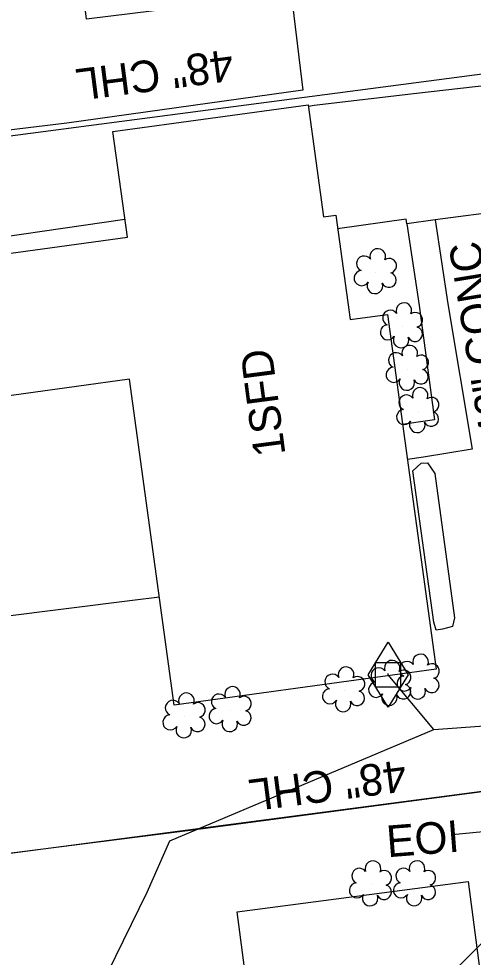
# Model space of a CAD drawing. Extents: x 2364404 to 2371833, y 798876 to 809754.
# Drawn here: x 2368310.1 to 2368367.6, y 807455.3 to 807574.1 of the extents above; entities that cross this region are included whole.
import ezdxf

# ---------------------------------------------------------------- set-up
doc = ezdxf.new("R2010")
doc.units = 0
for name, color, linetype in [('CTL Supplemental Horizontal and Vertical CELL', 7, 'Continuous'), ('Exist Building', 7, 'Continuous'), ('Exist Building Text', 7, 'Continuous'), ('Exist Other Culture Area Outline', 7, 'Continuous'), ('Exist Other Culture Area Outline Text', 7, 'Continuous'), ('Exist Other Culture Fence Line', 7, 'Continuous'), ('Exist Other Culture Fence Line Text', 7, 'Continuous'), ('Exist Property Line', 7, 'Continuous'), ('Exist Roads EOP Other', 7, 'Continuous'), ('Exist Utilities Gas Meter CELL', 7, 'Continuous'), ('Exist Utilities Gas UG Line SUE LOS B', 7, 'Continuous'), ('Exist Utilities Telephone UG Cable SUE LOS C', 7, 'Continuous'), ('Exist Utilities Telephone UG Cable SUE LOS C Text', 7, 'Continuous'), ('Exist Vegetation Hedge Row', 7, 'Continuous'), ('Exist Vegetation Shrub CELL', 7, 'Continuous')]:
    doc.layers.add(name, color=color, linetype=linetype)

msp = doc.modelspace()

# ---------------------------------------------------------------- linework, layer by layer
at = {"layer": 'CTL Supplemental Horizontal and Vertical CELL'}
msp.add_lwpolyline([(2368312.4, 807400.83), (2368379.23, 807467.66), (2368446.17, 807400.72), (2368379.35, 807333.89)], close=True, dxfattribs=at)
at = {"layer": 'Exist Building'}
for points in [[(2368318.69, 807574.03), (2368314.02, 807611.56), (2368304.65, 807610.39), (2368302.81, 807625.16), (2368311.97, 807626.3), (2368311.81, 807627.59), (2368339.99, 807631.09), (2368341.48, 807619.07), (2368346.02, 807619.64), (2368349.22, 807593.91), (2368344.46, 807593.32), (2368346.43, 807577.48)], [(2368329.78, 807487.21), (2368324.12, 807528.47), (2368303.93, 807525.7), (2368303.52, 807528.73), (2368293.29, 807527.33), (2368291.45, 807540.78), (2368301.53, 807542.17), (2368301.37, 807543.37), (2368323.84, 807546.45), (2368322.01, 807559.82), (2368346.71, 807563.2), (2368348.65, 807549.02), (2368350.21, 807549.23), (2368352.02, 807536.02), (2368356.75, 807536.67), (2368362.91, 807491.76)], [(2368366.97, 807464.89), (2368373.94, 807411.7), (2368344.89, 807407.89), (2368344.02, 807414.48), (2368340.29, 807413.99), (2368339.28, 807421.68), (2368342.85, 807422.14), (2368337.75, 807461.06)]]:
    msp.add_lwpolyline(points, close=True, dxfattribs=at)
msp.add_lwpolyline([(2368327.9, 807500.88), (2368324.48, 807500.46), (2368307.67, 807498.36), (2368290.09, 807495.99)], dxfattribs=at)
at = {"layer": 'Exist Other Culture Area Outline'}
for points in [[(2368323.53, 807548.68), (2368300.23, 807545.3), (2368300.67, 807542.05)], [(2368362.81, 807548.61), (2368364.39, 807537.99), (2368367.46, 807519.62), (2368361.32, 807518.58), (2368359.27, 807518.3)], [(2368359.22, 807548.14), (2368360.78, 807537.79), (2368362.72, 807523.31), (2368360.64, 807523.02), (2368358.66, 807522.75)]]:
    msp.add_lwpolyline(points, dxfattribs=at)
at = {"layer": 'Exist Other Culture Fence Line'}
for points in [[(2368344.58, 807577.25), (2368346.06, 807565.03), (2368316.19, 807560.86), (2368282.99, 807556.84)], [(2368406.44, 807474.54), (2368405.51, 807481.15), (2368370.62, 807476.49), (2368333.09, 807471.52), (2368294.55, 807466.63)]]:
    msp.add_lwpolyline(points, dxfattribs=at)
at = {"layer": 'Exist Property Line'}
for p, q in [((2368235.72, 807549.63), (2368401.5, 807571.4)), ((2368247.44, 807460.4), (2368413.11, 807482.15))]:
    msp.add_line(p, q, dxfattribs=at)
at = {"layer": 'Exist Roads EOP Other'}
for points in [[(2368402.89, 807569.36), (2368392.04, 807568.3), (2368381.2, 807566.99), (2368360.42, 807564.6), (2368347.48, 807563.08), (2368346.74, 807562.98)], [(2368419.04, 807554.27), (2368416.41, 807554.9), (2368409.89, 807554.57), (2368404.81, 807553.96), (2368393.72, 807552.85), (2368380.94, 807550.99), (2368362.81, 807548.61)], [(2368362.81, 807548.61), (2368359.22, 807548.14), (2368359.14, 807548.72), (2368350.45, 807547.5)]]:
    msp.add_lwpolyline(points, dxfattribs=at)
at = {"layer": 'Exist Utilities Gas Meter CELL'}
msp.add_line((2368356.83, 807491.07), (2368356.83, 807491.07), dxfattribs=at)
for points in [[(2368354.3, 807491.07), (2368356.83, 807495.18), (2368359.37, 807491.07), (2368356.83, 807486.96), (2368354.3, 807491.07)], [(2368355.26, 807492.61), (2368358.41, 807492.61), (2368358.41, 807489.5), (2368355.26, 807489.5), (2368355.26, 807492.61)]]:
    msp.add_lwpolyline(points, dxfattribs=at)
at = {"layer": 'Exist Utilities Gas UG Line SUE LOS B'}
for points in [[(2368313, 807431.3), (2368315.43, 807441.24), (2368326.34, 807463.56), (2368329.2, 807470.06), (2368362.61, 807484.12), (2368377.08, 807485.2), (2368429.76, 807491.87), (2368452.98, 807496.64)], [(2368362.61, 807484.12), (2368356.83, 807491.07), (2368356.86, 807491.23)]]:
    msp.add_lwpolyline(points, dxfattribs=at)
at = {"layer": 'Exist Utilities Telephone UG Cable SUE LOS C'}
msp.add_lwpolyline([(2368364.95, 807470.85), (2368412.03, 807475.41), (2368424.04, 807476.34), (2368428.94, 807482.47), (2368429.41, 807486.55), (2368425.74, 807516.43), (2368418.77, 807563.45), (2368413.38, 807612.29), (2368409.9, 807634.21), (2368405.63, 807637.87), (2368398.67, 807639.34), (2368392.73, 807633.04), (2368391.83, 807625.63), (2368393.11, 807623.54)], dxfattribs=at)
at = {"layer": 'Exist Vegetation Hedge Row'}
msp.add_lwpolyline([(2368362.73, 807516.55), (2368365.22, 807498.26), (2368364.97, 807497.19), (2368363.71, 807496.82), (2368362.93, 807496.72), (2368362.62, 807497.72), (2368359.97, 807516.86), (2368361, 807517.83), (2368361.81, 807517.88), (2368362.73, 807516.55)], dxfattribs=at)
at = {"layer": 'Exist Vegetation Shrub CELL'}
for p, q in [((2368355.29, 807541.95), (2368355.29, 807541.95)), ((2368358.6, 807535.1), (2368358.6, 807535.1)), ((2368359.34, 807529.72), (2368359.34, 807529.72)), ((2368360.66, 807524.37), (2368360.66, 807524.37)), ((2368360.71, 807490.66), (2368360.71, 807490.66)), ((2368351.28, 807489.04), (2368351.28, 807489.04)), ((2368357.12, 807489.86), (2368357.12, 807489.86)), ((2368336.92, 807486.54), (2368336.92, 807486.54)), ((2368331.09, 807485.74), (2368331.09, 807485.74)), ((2368354.69, 807464.49), (2368354.69, 807464.49)), ((2368360.26, 807464.5), (2368360.26, 807464.5))]:
    msp.add_line(p, q, dxfattribs=at)
for centre, radius, start, end in [((2368355.52, 807543.99), 0.99, 334.8391, 200.4717), ((2368353.81, 807543.08), 0.968, 35.8908, 245.4216), ((2368356.97, 807542.82), 0.929, 284.4567, 126.0861), ((2368353.49, 807541.25), 0.955, 95.1099, 327.9534), ((2368356.93, 807541.02), 0.937, 204.9913, 73.4601), ((2368355.17, 807540.27), 0.984, 151.2797, 21.387), ((2368358.83, 807537.14), 0.99, 334.8391, 200.4717), ((2368357.12, 807536.23), 0.968, 35.8908, 245.4216), ((2368360.27, 807535.97), 0.929, 284.4567, 126.0861), ((2368356.8, 807534.4), 0.955, 95.1099, 327.9534), ((2368360.24, 807534.17), 0.937, 204.9913, 73.4601), ((2368358.47, 807533.42), 0.984, 151.2797, 21.387), ((2368357.86, 807530.85), 0.968, 35.8908, 245.4216), ((2368359.57, 807531.76), 0.99, 334.8391, 200.4717), ((2368361.01, 807530.59), 0.929, 284.4567, 126.0861), ((2368357.54, 807529.02), 0.955, 95.1099, 327.9534), ((2368360.98, 807528.79), 0.937, 204.9913, 73.4601), ((2368359.21, 807528.04), 0.984, 151.2797, 21.387), ((2368360.89, 807526.41), 0.99, 334.8391, 200.4717), ((2368359.17, 807525.5), 0.968, 35.8908, 245.4216), ((2368362.33, 807525.24), 0.929, 284.4567, 126.0861), ((2368358.86, 807523.67), 0.955, 95.1099, 327.9534), ((2368362.29, 807523.44), 0.937, 204.9913, 73.4601), ((2368360.53, 807522.69), 0.984, 151.2797, 21.387), ((2368360.94, 807492.7), 0.99, 334.8391, 200.4717), ((2368357.35, 807491.9), 0.99, 334.8391, 200.4717), ((2368359.23, 807491.79), 0.968, 35.8908, 245.4216), ((2368362.38, 807491.53), 0.929, 284.4567, 126.0861), ((2368351.51, 807491.08), 0.99, 334.8391, 200.4717), ((2368355.64, 807490.99), 0.968, 35.8908, 245.4216), ((2368358.79, 807490.73), 0.929, 284.4567, 126.0861), ((2368349.8, 807490.17), 0.968, 35.8908, 245.4216), ((2368352.95, 807489.91), 0.929, 284.4567, 126.0861), ((2368355.32, 807489.16), 0.955, 95.1099, 327.9534), ((2368358.91, 807489.96), 0.955, 95.1099, 327.9534), ((2368362.35, 807489.73), 0.937, 204.9913, 73.4601), ((2368337.15, 807488.58), 0.99, 334.8391, 200.4717), ((2368349.48, 807488.34), 0.955, 95.1099, 327.9534), ((2368352.92, 807488.11), 0.937, 204.9913, 73.4601), ((2368358.76, 807488.93), 0.937, 204.9913, 73.4601), ((2368360.58, 807488.98), 0.984, 151.2797, 21.387), ((2368329.61, 807486.87), 0.968, 35.8908, 245.4216), ((2368331.32, 807487.78), 0.99, 334.8391, 200.4717), ((2368335.44, 807487.66), 0.968, 35.8908, 245.4216), ((2368338.59, 807487.41), 0.929, 284.4567, 126.0861), ((2368351.15, 807487.36), 0.984, 151.2797, 21.387), ((2368356.99, 807488.18), 0.984, 151.2797, 21.387), ((2368332.77, 807486.61), 0.929, 284.4567, 126.0861), ((2368335.12, 807485.83), 0.955, 95.1099, 327.9534), ((2368338.56, 807485.61), 0.937, 204.9913, 73.4601), ((2368329.29, 807485.04), 0.955, 95.1099, 327.9534), ((2368332.73, 807484.81), 0.937, 204.9913, 73.4601), ((2368336.79, 807484.85), 0.984, 151.2797, 21.387), ((2368330.97, 807484.06), 0.984, 151.2797, 21.387), ((2368354.92, 807466.53), 0.99, 334.8391, 200.4717), ((2368360.49, 807466.54), 0.99, 334.8391, 200.4717), ((2368353.21, 807465.61), 0.968, 35.8908, 245.4216), ((2368356.36, 807465.36), 0.929, 284.4567, 126.0861), ((2368358.78, 807465.62), 0.968, 35.8908, 245.4216), ((2368361.93, 807465.37), 0.929, 284.4567, 126.0861), ((2368352.89, 807463.78), 0.955, 95.1099, 327.9534), ((2368356.32, 807463.56), 0.937, 204.9913, 73.4601), ((2368358.46, 807463.79), 0.955, 95.1099, 327.9534), ((2368361.9, 807463.57), 0.937, 204.9913, 73.4601), ((2368354.56, 807462.8), 0.984, 151.2797, 21.387), ((2368360.13, 807462.81), 0.984, 151.2797, 21.387)]:
    msp.add_arc(centre, radius, start, end, dxfattribs=at)

# ---------------------------------------------------------------- texts
at = {"layer": 'Exist Building Text'}
msp.add_text('1SFD', height=4, rotation=97.4798, dxfattribs=at).set_placement((2368343.86, 807518.95))
at = {"layer": 'Exist Other Culture Area Outline Text'}
msp.add_text('42" CONC', height=4, rotation=99.2972, dxfattribs=at).set_placement((2368372.48, 807521.38))
at = {"layer": 'Exist Other Culture Fence Line Text'}
for p in [(2368336.98, 807570.23), (2368358.87, 807480.32)]:
    msp.add_text('48" CHL', height=4, rotation=187.3757, dxfattribs=at).set_placement(p)
at = {"layer": 'Exist Utilities Telephone UG Cable SUE LOS C Text'}
msp.add_text('EOI', height=4, rotation=4.523, dxfattribs=at).set_placement((2368356.78, 807467.97))

doc.saveas('drawing.dxf')
